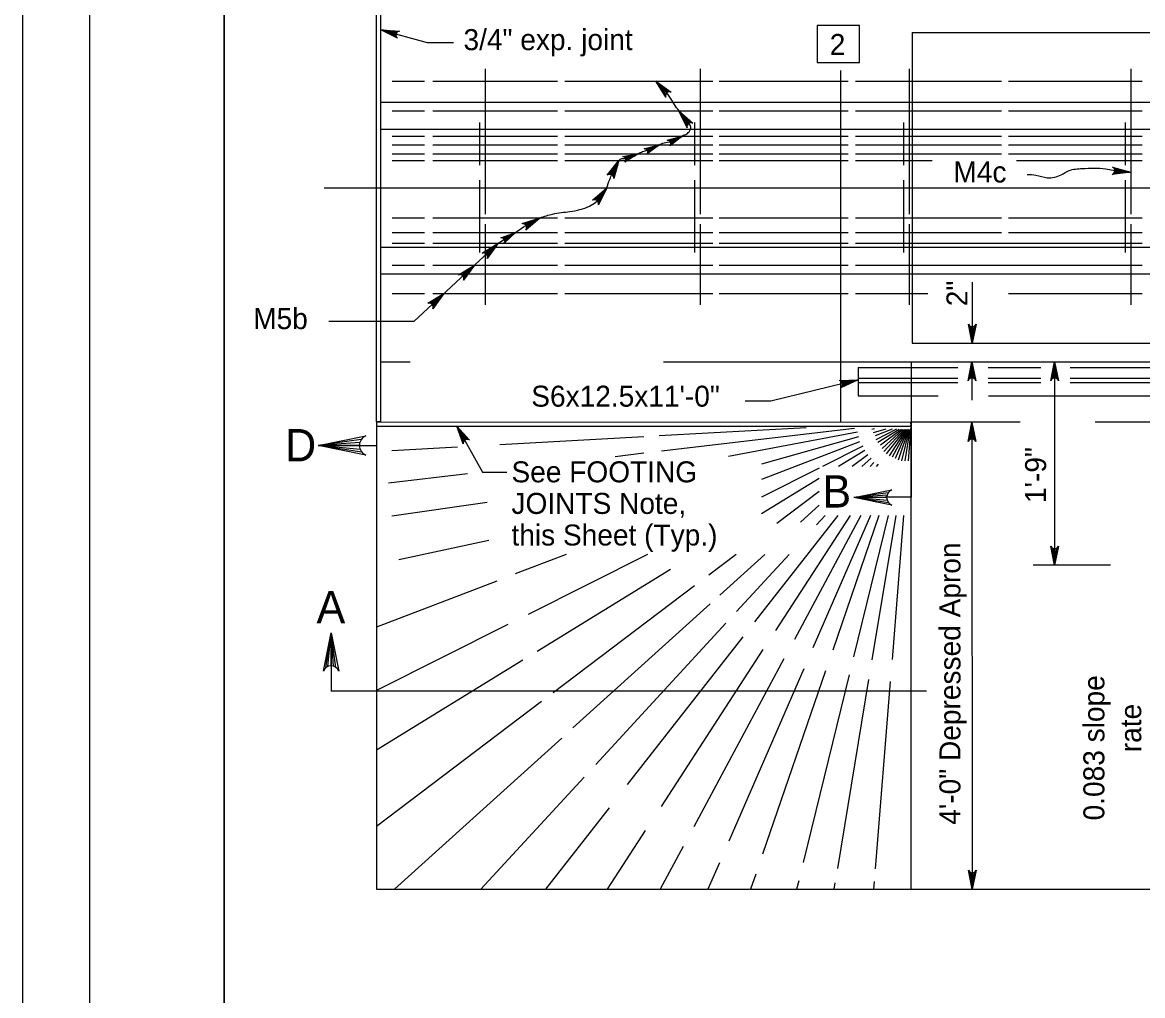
# Model space of a CAD drawing. Extents: x 0 to 34, y 0 to 22.
# Drawn here: x 0 to 8.32, y 10.41 to 17.63 of the extents above; entities that cross this region are included whole.
import ezdxf

# ---------------------------------------------------------------- set-up
doc = ezdxf.new("R2010")
doc.units = 0
for name, color, linetype in [('Default', 7, 'Continuous'), ('SH_Border', 7, 'Continuous'), ('SH_Cut_Line', 7, 'Continuous')]:
    doc.layers.add(name, color=color, linetype=linetype)

msp = doc.modelspace()

# ---------------------------------------------------------------- linework, layer by layer
at = {"layer": 'Default'}
for p, q in [((2.6299, 14.754), (2.6299, 18.1355)), ((2.6619, 14.754), (2.6619, 18.1355)), ((2.7767, 17.549), (2.6619, 17.58)), ((2.7759, 17.5375), (2.6619, 17.58)), ((2.7784, 17.5285), (2.6619, 17.58)), ((2.7802, 17.5571), (2.6619, 17.58)), ((2.7866, 17.5642), (2.6619, 17.58)), ((5.9052, 17.6119), (5.9052, 17.3364)), ((6.2195, 17.6119), (5.9052, 17.6119)), ((6.2195, 17.3364), (6.2195, 17.6119)), ((6.6102, 17.5605), (13.4816, 17.5605)), ((6.6102, 17.5605), (6.6102, 15.2526)), ((5.9052, 17.3364), (6.2195, 17.3364)), ((3.4374, 17.2901), (3.4374, 16.211)), ((5.0367, 17.2901), (5.0367, 16.211)), ((6.0797, 14.8717), (6.0797, 17.2778)), ((6.5879, 17.2901), (6.5879, 16.211)), ((8.2352, 17.2901), (8.2352, 16.211)), ((2.7462, 17.1978), (2.9867, 17.1978)), ((3.0502, 17.1978), (3.9757, 17.1978)), ((4.0302, 17.1978), (5.1292, 17.1978)), ((4.788, 17.1114), (4.7064, 17.1978)), ((4.7814, 17.1021), (4.7064, 17.1978)), ((4.7787, 17.0931), (4.7064, 17.1978)), ((4.7953, 17.1164), (4.7064, 17.1978)), ((4.8044, 17.1193), (4.7064, 17.1978)), ((5.1759, 17.1978), (6.1347, 17.1978)), ((6.1886, 17.1978), (7.2741, 17.1978)), ((7.3255, 17.1978), (8.3184, 17.1978)), ((2.6587, 17.0425), (13.2226, 17.0425)), ((2.7462, 16.9791), (2.9867, 16.9791)), ((3.0502, 16.9791), (3.9757, 16.9791)), ((4.0302, 16.9791), (5.1292, 16.9791)), ((4.9492, 16.8839), (4.878, 16.9791)), ((4.9416, 16.8754), (4.878, 16.9791)), ((4.938, 16.8668), (4.878, 16.9791)), ((4.957, 16.888), (4.878, 16.9791)), ((4.9665, 16.8899), (4.878, 16.9791)), ((5.1759, 16.9791), (6.1347, 16.9791)), ((6.1886, 16.9791), (7.2741, 16.9791)), ((7.3255, 16.9791), (8.3184, 16.9791)), ((2.6587, 16.8425), (13.2226, 16.8425)), ((3.3954, 16.892), (3.3954, 16.5743)), ((4.9947, 16.892), (4.9947, 16.5743)), ((6.5459, 16.892), (6.5459, 16.5743)), ((8.1932, 16.892), (8.1932, 16.5743)), ((2.7462, 16.7906), (2.9867, 16.7906)), ((3.0502, 16.7906), (3.9757, 16.7906)), ((4.0302, 16.7906), (5.1292, 16.7906)), ((4.8027, 16.7571), (4.9013, 16.7904)), ((4.8092, 16.7531), (4.9013, 16.7904)), ((4.8149, 16.7459), (4.9013, 16.7904)), ((4.8172, 16.739), (4.9013, 16.7904)), ((4.8173, 16.7311), (4.9013, 16.7904)), ((5.1759, 16.7906), (6.1347, 16.7906)), ((6.1886, 16.7906), (7.2741, 16.7906)), ((7.3255, 16.7906), (8.3184, 16.7906)), ((2.7462, 16.7252), (2.9867, 16.7252)), ((2.7462, 16.6597), (2.9867, 16.6597)), ((3.0502, 16.7252), (3.9757, 16.7252)), ((3.0502, 16.6597), (3.9757, 16.6597)), ((4.0302, 16.7252), (5.1292, 16.7252)), ((4.0302, 16.6597), (5.1292, 16.6597)), ((4.4713, 16.6351), (4.5727, 16.6594)), ((4.4774, 16.6306), (4.5727, 16.6594)), ((4.4826, 16.6228), (4.5727, 16.6594)), ((4.4837, 16.6079), (4.5727, 16.6594)), ((4.4842, 16.6157), (4.5727, 16.6594)), ((4.6312, 16.6935), (4.7305, 16.7252)), ((4.6377, 16.6893), (4.7305, 16.7252)), ((4.6433, 16.682), (4.7305, 16.7252)), ((4.6456, 16.675), (4.7305, 16.7252)), ((4.6457, 16.6671), (4.7305, 16.7252)), ((5.1759, 16.7252), (6.1347, 16.7252)), ((5.1759, 16.6597), (6.1347, 16.6597)), ((6.1886, 16.7252), (7.2741, 16.7252)), ((6.1886, 16.6597), (7.2741, 16.6597)), ((7.3255, 16.7252), (8.3184, 16.7252)), ((7.3255, 16.6597), (8.3184, 16.6597)), ((2.7462, 16.6092), (2.9867, 16.6092)), ((3.0502, 16.6092), (3.9757, 16.6092)), ((4.0302, 16.6092), (5.1292, 16.6092)), ((4.3584, 16.5055), (4.4325, 16.6092)), ((4.3678, 16.5061), (4.4325, 16.6092)), ((4.3787, 16.503), (4.4325, 16.6092)), ((4.386, 16.498), (4.4325, 16.6092)), ((4.3918, 16.4903), (4.4325, 16.6092)), ((5.1759, 16.6092), (6.1347, 16.6092)), ((6.1886, 16.6092), (6.7603, 16.6092)), ((7.3851, 16.6092), (8.3184, 16.6092)), ((8.1097, 16.5143), (8.2352, 16.5221)), ((8.1111, 16.551), (8.2352, 16.5221)), ((8.1146, 16.5225), (8.2352, 16.5221)), ((8.1152, 16.5425), (8.2352, 16.5221)), ((8.1165, 16.5312), (8.2352, 16.5221)), ((2.2418, 16.4059), (13.2226, 16.4059)), ((3.3954, 16.4632), (3.3954, 15.9257)), ((4.25, 16.3174), (4.3415, 16.4059)), ((4.2592, 16.3162), (4.3415, 16.4059)), ((4.2696, 16.3112), (4.3415, 16.4059)), ((4.2757, 16.3049), (4.3415, 16.4059)), ((4.2801, 16.2963), (4.3415, 16.4059)), ((4.9947, 16.4632), (4.9947, 15.9257)), ((6.5459, 16.4632), (6.5459, 15.9257)), ((8.1932, 16.4632), (8.1932, 15.9257)), ((2.7462, 16.183), (2.9867, 16.183)), ((3.0502, 16.183), (3.9757, 16.183)), ((3.7271, 16.1382), (3.8462, 16.183)), ((3.7352, 16.1335), (3.8462, 16.183)), ((3.7425, 16.1249), (3.8462, 16.183)), ((3.7457, 16.1166), (3.8462, 16.183)), ((3.7462, 16.107), (3.8462, 16.183)), ((4.0302, 16.183), (5.1292, 16.183)), ((5.1759, 16.183), (6.1347, 16.183)), ((6.1886, 16.183), (7.2741, 16.183)), ((7.3255, 16.183), (8.3184, 16.183)), ((2.7462, 16.0737), (2.9867, 16.0737)), ((3.0502, 16.0737), (3.9757, 16.0737)), ((3.4374, 16.1359), (3.4374, 15.5359)), ((3.5666, 16.0335), (3.6627, 16.0737)), ((3.5733, 16.0299), (3.6627, 16.0737)), ((3.5797, 16.023), (3.6627, 16.0737)), ((3.5825, 16.0163), (3.6627, 16.0737)), ((3.5832, 16.0085), (3.6627, 16.0737)), ((4.0302, 16.0737), (5.1292, 16.0737)), ((5.0367, 16.1359), (5.0367, 15.5359)), ((5.1759, 16.0737), (6.1347, 16.0737)), ((6.1886, 16.0737), (7.2741, 16.0737)), ((6.5879, 16.1359), (6.5879, 15.5359)), ((7.3255, 16.0737), (8.3184, 16.0737)), ((8.2352, 16.1359), (8.2352, 15.5359)), ((2.7462, 15.9945), (2.9867, 15.9945)), ((3.5347, 15.9945), (2.9075, 15.4138)), ((3.0502, 15.9945), (3.9757, 15.9945)), ((3.429, 15.9233), (3.5347, 15.9945)), ((3.438, 15.9205), (3.5347, 15.9945)), ((3.4472, 15.9138), (3.5347, 15.9945)), ((3.4522, 15.9065), (3.5347, 15.9945)), ((3.4549, 15.8973), (3.5347, 15.9945)), ((4.0302, 15.9945), (5.1292, 15.9945)), ((5.1759, 15.9945), (6.1347, 15.9945)), ((6.1886, 15.9945), (7.3255, 15.9945)), ((7.3255, 15.9945), (8.3184, 15.9945)), ((2.6587, 15.9659), (7.3622, 15.9659)), ((7.3252, 15.9659), (13.2226, 15.9659)), ((2.7462, 15.832), (2.9867, 15.832)), ((3.0502, 15.832), (3.9757, 15.832)), ((3.253, 15.7611), (3.3587, 15.8323)), ((3.262, 15.7585), (3.3587, 15.8323)), ((3.2712, 15.7517), (3.3587, 15.8323)), ((3.2762, 15.7444), (3.3587, 15.8323)), ((3.2789, 15.7352), (3.3587, 15.8323)), ((4.0302, 15.832), (5.1292, 15.832)), ((5.1759, 15.832), (6.1347, 15.832)), ((6.1886, 15.832), (7.3255, 15.832)), ((7.3255, 15.832), (8.3184, 15.832)), ((2.6587, 15.7663), (7.3252, 15.7663)), ((7.3252, 15.7663), (13.2226, 15.7663)), ((7.0568, 15.7059), (7.0568, 15.2526)), ((2.7462, 15.621), (2.9867, 15.621)), ((3.0259, 15.5497), (3.1316, 15.6208)), ((3.0349, 15.547), (3.1316, 15.6208)), ((3.0441, 15.5402), (3.1316, 15.6208)), ((3.0491, 15.5329), (3.1316, 15.6208)), ((3.0502, 15.621), (3.9757, 15.621)), ((3.0518, 15.5237), (3.1316, 15.6208)), ((4.0302, 15.621), (5.1292, 15.621)), ((5.1759, 15.621), (6.1347, 15.621)), ((6.1886, 15.621), (6.7267, 15.621)), ((7.3255, 15.621), (8.3184, 15.621)), ((2.9075, 15.4138), (2.2767, 15.4138)), ((7.0389, 15.3808), (7.0568, 15.2526)), ((7.0477, 15.3765), (7.0568, 15.2526)), ((7.0767, 15.3823), (7.0568, 15.2526)), ((7.0683, 15.3774), (7.0568, 15.2526)), ((7.0568, 15.3751), (7.0568, 15.2526)), ((6.6102, 15.2526), (13.4572, 15.2526)), ((2.6587, 15.1145), (2.8801, 15.1145)), ((4.7623, 15.1145), (13.2169, 15.1145)), ((6.2088, 15.0704), (6.2088, 14.8604)), ((6.2088, 15.0704), (6.9505, 15.0704)), ((6.6032, 15.1145), (6.6032, 14.6664)), ((7.0352, 14.9849), (7.055, 15.1145)), ((7.0435, 14.9898), (7.055, 15.1145)), ((7.055, 14.992), (7.055, 15.1145)), ((7.0641, 14.9907), (7.055, 15.1145)), ((7.0729, 14.9864), (7.055, 15.1145)), ((7.055, 15.1145), (7.055, 14.8292)), ((7.1763, 15.0704), (7.5665, 15.0704)), ((7.6492, 14.9849), (7.6689, 15.1145)), ((7.6574, 14.9898), (7.6689, 15.1145)), ((7.6689, 15.1145), (7.6689, 13.6028)), ((7.6689, 14.992), (7.6689, 15.1145)), ((7.678, 14.9907), (7.6689, 15.1145)), ((7.6869, 14.9864), (7.6689, 15.1145)), ((7.7847, 15.0704), (13.2147, 15.0704)), ((6.2088, 14.9931), (6.9505, 14.9931)), ((7.1763, 14.9931), (7.5665, 14.9931)), ((7.7847, 14.9931), (13.2147, 14.9931)), ((6.2088, 14.9785), (5.5602, 14.8218)), ((6.0818, 14.9688), (6.2088, 14.9785)), ((6.0883, 14.962), (6.2088, 14.9785)), ((6.0916, 14.9334), (6.2088, 14.9785)), ((6.093, 14.9516), (6.2088, 14.9785)), ((6.0937, 14.9427), (6.2088, 14.9785)), ((6.2088, 14.9605), (6.9505, 14.9605)), ((7.1763, 14.9605), (7.5665, 14.9605)), ((7.7847, 14.9605), (13.2147, 14.9605)), ((5.5602, 14.8218), (5.3711, 14.8218)), ((6.0797, 14.6664), (6.0797, 14.8717)), ((6.2088, 14.8604), (6.8027, 14.8604)), ((7.1775, 14.8604), (13.2147, 14.8604)), ((2.6299, 14.6664), (2.6299, 14.754)), ((2.6619, 14.6664), (2.6619, 14.754)), ((2.6299, 14.6664), (2.6587, 14.6664)), ((2.6299, 14.6664), (2.6299, 14.5643)), ((2.6299, 14.6664), (2.6299, 14.4918)), ((2.6619, 14.6664), (2.6331, 14.6664)), ((2.6587, 14.6664), (6.5998, 14.6661)), ((6.6032, 14.6664), (6.5802, 14.379)), ((6.6032, 14.6664), (6.5983, 14.6368)), ((6.6032, 14.6664), (6.599, 14.649)), ((6.6032, 14.6664), (6.5992, 14.6548)), ((6.6032, 14.6664), (6.5994, 14.6575)), ((6.6032, 14.6664), (6.5995, 14.6594)), ((6.6032, 14.6664), (6.5996, 14.6607)), ((6.6032, 14.6664), (6.5997, 14.6646)), ((6.6032, 14.6664), (6.5997, 14.6642)), ((6.6032, 14.6664), (6.5997, 14.6637)), ((6.6032, 14.6664), (6.5997, 14.6631)), ((6.6032, 14.6664), (6.5997, 14.6625)), ((6.6032, 14.6664), (6.5997, 14.6617)), ((6.6032, 14.6664), (6.5998, 14.6661)), ((6.6032, 14.6664), (6.5998, 14.6657)), ((6.6032, 14.6664), (6.5998, 14.6654)), ((6.6032, 14.6664), (6.5998, 14.666)), ((6.6032, 14.6664), (6.5998, 14.665)), ((6.6032, 11.1951), (6.6032, 14.6664)), ((6.6032, 14.6664), (6.6032, 14.1067)), ((6.6032, 14.6664), (6.7953, 14.6664)), ((6.7953, 14.6664), (7.4136, 14.6664)), ((7.0352, 14.5326), (7.055, 14.6623)), ((7.0435, 14.5375), (7.055, 14.6623)), ((7.055, 14.6623), (7.0568, 11.1951)), ((7.055, 14.5398), (7.055, 14.6623)), ((7.0641, 14.5385), (7.055, 14.6623)), ((7.0729, 14.5341), (7.055, 14.6623)), ((7.9699, 14.6664), (9.1479, 14.6664)), ((2.6299, 14.6349), (6.5998, 14.6347)), ((3.2884, 14.533), (3.227, 14.6349)), ((3.28, 14.5255), (3.227, 14.6349)), ((3.2755, 14.5171), (3.227, 14.6349)), ((3.2966, 14.5365), (3.227, 14.6349)), ((3.3061, 14.5373), (3.227, 14.6349)), ((5.8236, 14.6232), (4.7308, 14.5628)), ((6.1832, 14.6171), (4.7482, 14.449)), ((6.2051, 14.5909), (5.2467, 14.4092)), ((6.3306, 14.6147), (6.3122, 14.6112)), ((6.4143, 14.6133), (6.3208, 14.587)), ((6.4627, 14.6125), (6.3348, 14.5634)), ((6.4948, 14.6119), (6.3417, 14.535)), ((6.5139, 14.6115), (6.3553, 14.5143)), ((6.5305, 14.6113), (6.3766, 14.4949)), ((6.5422, 14.6111), (6.3868, 14.4706)), ((6.5522, 14.611), (6.4003, 14.446)), ((6.5597, 14.6108), (6.4186, 14.4305)), ((6.567, 14.6107), (6.4397, 14.4151)), ((6.5733, 14.6105), (6.4629, 14.4051)), ((6.579, 14.6105), (6.4848, 14.394)), ((6.584, 14.6104), (6.5057, 14.3826)), ((6.5895, 14.6103), (6.5326, 14.378)), ((6.594, 14.6102), (6.5555, 14.3773)), ((2.5177, 14.5366), (2.1972, 14.4918)), ((2.5069, 14.5145), (2.1972, 14.4918)), ((2.1972, 14.4918), (2.6299, 14.4918)), ((2.5036, 14.4918), (2.1972, 14.4918)), ((2.5092, 14.463), (2.1972, 14.4918)), ((2.5216, 14.4422), (2.1972, 14.4918)), ((2.6299, 14.5643), (2.6299, 11.1951)), ((4.6168, 14.5565), (3.5461, 14.4973)), ((6.2131, 14.5567), (5.4906, 14.3538)), ((6.2187, 14.5188), (5.4906, 14.2394)), ((6.2435, 14.4856), (5.9442, 14.3354)), ((3.2322, 14.4799), (2.7442, 14.4529)), ((4.6183, 14.4338), (4.4033, 14.4086)), ((6.2582, 14.4546), (6.0638, 14.3354)), ((6.2808, 14.4225), (6.1657, 14.3354)), ((5.9209, 14.3236), (5.4906, 14.1075)), ((6.3063, 14.3978), (6.2373, 14.3354)), ((6.3258, 14.3652), (6.2984, 14.3354)), ((6.3571, 14.352), (6.3442, 14.3354)), ((3.3068, 14.2801), (2.7193, 14.2113)), ((5.9209, 14.2477), (5.4906, 13.9837)), ((5.9209, 14.1501), (5.6062, 13.9121)), ((3.452, 14.0689), (2.7437, 13.9667)), ((6.4327, 14.1408), (6.1763, 14.105)), ((6.424, 14.123), (6.1763, 14.105)), ((6.4214, 14.105), (6.1763, 14.105)), ((6.4259, 14.0819), (6.1763, 14.105)), ((6.4357, 14.0653), (6.1763, 14.105)), ((6.485, 14.1067), (6.4113, 14.1067)), ((6.6032, 14.1067), (6.485, 14.1067)), ((5.9209, 14.0491), (5.7809, 13.9225)), ((6.0593, 13.9716), (5.4404, 13.1811)), ((6.151, 13.9716), (5.5955, 13.1182)), ((6.23, 13.9716), (5.7355, 13.051)), ((6.3012, 13.9716), (5.8735, 12.9881)), ((5.9632, 13.9716), (5.9003, 13.9034)), ((6.3643, 13.9716), (6.0205, 12.9714)), ((6.4329, 13.9716), (6.1754, 12.9216)), ((6.4884, 13.9716), (6.311, 12.8983)), ((6.5474, 13.9716), (6.4616, 12.9022)), ((3.4657, 13.785), (2.7977, 13.6416)), ((4.0402, 13.6827), (3.6623, 13.5377)), ((4.6447, 13.6827), (3.7565, 13.2365)), ((5.3031, 13.6827), (5.0993, 13.5286)), ((5.5157, 13.6827), (5.1811, 13.3801)), ((5.697, 13.6827), (5.3052, 13.2575)), ((7.651, 13.731), (7.6689, 13.6028)), ((7.6599, 13.7266), (7.6689, 13.6028)), ((7.6887, 13.7325), (7.6689, 13.6028)), ((7.6805, 13.7275), (7.6689, 13.6028)), ((7.6689, 13.7253), (7.6689, 13.6028)), ((4.8164, 13.5701), (3.8244, 12.9615)), ((8.085, 13.6028), (7.5091, 13.6028)), ((3.5243, 13.4848), (2.6299, 13.1415)), ((4.9936, 13.4486), (3.9428, 12.6536)), ((5.1097, 13.3156), (4.09, 12.3933)), ((3.6066, 13.1612), (2.6299, 12.6706)), ((5.2262, 13.1715), (4.2598, 12.1226)), ((2.2537, 12.84), (2.2933, 13.0994)), ((2.2702, 12.8498), (2.2933, 13.0994)), ((2.2933, 13.0994), (2.2933, 12.6667)), ((2.2933, 12.8543), (2.2933, 13.0994)), ((2.3114, 12.8517), (2.2933, 13.0994)), ((2.3292, 12.843), (2.2933, 13.0994)), ((5.3532, 13.0697), (4.4941, 11.9725)), ((5.5024, 12.9753), (4.7447, 11.811)), ((5.6585, 12.9078), (4.9878, 11.6593)), ((3.7176, 12.896), (2.6299, 12.2287)), ((5.8062, 12.8333), (5.2492, 11.5523)), ((5.9677, 12.8182), (5.4996, 11.4566)), ((6.1425, 12.7871), (5.8012, 11.3949)), ((6.287, 12.7535), (6.0548, 11.349)), ((6.4485, 12.7395), (6.3366, 11.3464)), ((6.7182, 12.6667), (2.2933, 12.6667)), ((3.8578, 12.5893), (2.6299, 11.6604)), ((4.0075, 12.3185), (2.7654, 11.1951)), ((4.1727, 12.028), (3.4054, 11.1951)), ((4.3591, 11.8), (3.8855, 11.1951)), ((4.6278, 11.6316), (4.3437, 11.1951)), ((4.909, 11.5125), (4.7385, 11.1951)), ((5.1792, 11.3915), (5.0938, 11.1951)), ((7.0389, 11.3234), (7.0568, 11.1951)), ((7.0477, 11.319), (7.0568, 11.1951)), ((7.0767, 11.3249), (7.0568, 11.1951)), ((7.0683, 11.32), (7.0568, 11.1951)), ((5.4481, 11.3068), (5.4097, 11.1951)), ((5.7677, 11.2585), (5.7522, 11.1951)), ((6.0373, 11.2432), (6.0294, 11.1951)), ((6.329, 11.2515), (6.3244, 11.1951)), ((7.0568, 11.3177), (7.0568, 11.1951)), ((2.6299, 11.1951), (18.4777, 11.1951))]:
    msp.add_line(p, q, dxfattribs=at)
for points in [[(2.7874, 17.5175), (2.6619, 17.58), (2.8017, 17.5706)], [(2.6619, 17.58), (3.008, 17.4844), (3.204, 17.4844)], [(4.7807, 17.079), (4.7064, 17.1978), (4.8207, 17.1167)], [(4.9383, 16.8525), (4.878, 16.9791), (4.9823, 16.8855)], [(4.7911, 16.7588), (4.9013, 16.7904), (4.8117, 16.7189)], [(4.4599, 16.6378), (4.5727, 16.6594), (4.477, 16.5963)], [(4.6197, 16.6953), (4.7305, 16.7252), (4.6397, 16.655)], [(4.3459, 16.499), (4.4325, 16.6092), (4.395, 16.4741)], [(8.1002, 16.56), (8.2352, 16.5221), (8.096, 16.5052)], [(4.2364, 16.3131), (4.3415, 16.4059), (4.2802, 16.2798)], [(3.7129, 16.1399), (3.8462, 16.183), (3.7398, 16.0919)], [(3.555, 16.0343), (3.6627, 16.0737), (3.5784, 15.996)], [(3.4149, 15.9215), (3.5347, 15.9945), (3.4522, 15.8811)], [(3.239, 15.7594), (3.3587, 15.8323), (3.2762, 15.719)], [(3.0118, 15.5479), (3.1316, 15.6208), (3.0491, 15.5075)], [(7.0852, 15.3942), (7.0568, 15.2526), (7.0285, 15.3942)], [(7.0267, 14.973), (7.055, 15.1145), (7.0833, 14.973)], [(7.6407, 14.973), (7.6689, 15.1145), (7.6972, 14.973)], [(6.0687, 14.9742), (6.2088, 14.9785), (6.0812, 14.9207)], [(7.0267, 14.5207), (7.055, 14.6623), (7.0833, 14.5207)], [(3.2745, 14.503), (3.227, 14.6349), (3.3215, 14.5314)], [(3.227, 14.6349), (3.4185, 14.2932), (3.5981, 14.2932)], [(2.5512, 14.421), (2.1972, 14.4918), (2.5512, 14.5626)], [(6.4595, 14.0483), (6.1763, 14.105), (6.4595, 14.1615)], [(7.6972, 13.7444), (7.6689, 13.6028), (7.6407, 13.7444)], [(2.2367, 12.8162), (2.2933, 13.0994), (2.3499, 12.8162)], [(7.0852, 11.3368), (7.0568, 11.1951), (7.0285, 11.3368)]]:
    msp.add_lwpolyline(points, dxfattribs=at)
for centre, radius, start, end in [((7.0568, 15.4057), 0.0306, 202.08782, 337.91395), ((7.055, 14.9615), 0.0306, 22.08782, 157.91395), ((7.669, 14.9615), 0.0306, 22.08782, 157.91395), ((2.5799, 14.4919), 0.0764, 112.08782, 247.91395), ((7.055, 14.5093), 0.0306, 22.08782, 157.91395), ((6.4824, 14.105), 0.0611, 112.08782, 247.91395), ((7.6689, 13.7558), 0.0306, 202.08782, 337.91395), ((2.2933, 12.7933), 0.0611, 22.08782, 157.91395), ((7.0568, 11.3482), 0.0306, 202.08782, 337.91395)]:
    msp.add_arc(centre, radius, start, end, dxfattribs=at)
for centre, major_axis, start_param, end_param in [((2.8053, 17.5412), (-0.0296, 0.0021), 4.904467, 7.27508), ((4.8084, 17.0898), (0.0297, 0), 1.141672, 3.512285), ((4.967, 16.8601), (0.0297, 0), 1.027626, 3.398239), ((4.7932, 16.7347), (0.0243, 0), 5.57401, 7.944623), ((4.6216, 16.6711), (0.0243, 0), 5.55876, 7.929373), ((4.46, 16.6137), (0.0243, 0), 5.483661, 7.854274), ((4.3654, 16.4766), (0.0297, 0), 6.20027, 8.570883), ((8.087, 16.5335), (0.0297, 0), 5.021719, 7.392332), ((4.2516, 16.2876), (0.0297, 0), 6.01866, 8.389273), ((3.7166, 16.1104), (0.0297, 0), 5.608673, 7.979286), ((3.5589, 16.0103), (0.0243, 0), 5.645901, 8.016514), ((3.4254, 15.8938), (0.0297, 0), 5.842591, 8.213204), ((3.2494, 15.7316), (0.0297, 0), 5.842591, 8.213204), ((3.0223, 15.5201), (0.0297, 0), 5.842591, 8.213204), ((6.0641, 14.9449), (0.0297, 0), 5.325468, 7.696081), ((3.3037, 14.5076), (0.0232, 0.0184), 0.257527, 2.62814)]:
    msp.add_ellipse(centre, major_axis=major_axis, ratio=0.999895, start_param=start_param, end_param=end_param, dxfattribs=at)
for points in [[(4.8786, 16.9783), (4.8441, 17.0249), (4.8064, 17.0874), (4.7617, 17.1392), (4.7064, 17.1978)], [(4.9017, 16.7906), (4.9112, 16.7965), (4.9289, 16.8026), (4.9527, 16.8217), (4.9649, 16.8415), (4.9669, 16.8591), (4.9608, 16.8707), (4.931, 16.9087), (4.9011, 16.9482), (4.878, 16.9791)], [(4.7305, 16.7252), (4.7483, 16.734), (4.7904, 16.7449), (4.8652, 16.7666), (4.9017, 16.7906)], [(4.4325, 16.6092), (4.4422, 16.6197), (4.4692, 16.6234), (4.5145, 16.6283), (4.5732, 16.6597)], [(4.5732, 16.6597), (4.5989, 16.671), (4.6364, 16.6847), (4.6729, 16.6965), (4.7305, 16.7252)], [(4.3415, 16.4059), (4.3639, 16.4689), (4.4042, 16.5535), (4.4325, 16.6092)], [(7.4657, 16.5045), (7.5302, 16.5005), (7.6144, 16.481), (7.7182, 16.5025), (7.7768, 16.5339), (7.8727, 16.5496), (8.0487, 16.5476), (8.1583, 16.528), (8.2352, 16.5221)], [(3.8462, 16.183), (3.9397, 16.2113), (4.068, 16.23), (4.2133, 16.2695), (4.2612, 16.3003), (4.3415, 16.4059)], [(3.6627, 16.0737), (3.7067, 16.1048), (3.8462, 16.183)], [(3.5347, 15.9945), (3.5882, 16.0282), (3.6627, 16.0737)]]:
    msp.add_spline(points, degree=3, dxfattribs=at)
at = {"layer": 'SH_Border'}
for points in [[(0.5, 21.5), (1.5, 21.5), (1.5, 0.5), (0.5, 0.5)], [(1.5, 21.5), (33.5, 21.5), (33.5, 0.5), (1.5, 0.5)]]:
    msp.add_lwpolyline(points, close=True, dxfattribs=at)
at = {"layer": 'SH_Cut_Line'}
msp.add_lwpolyline([(0, 0), (34, 0), (34, 22), (0, 22)], close=True, dxfattribs=at)

# ---------------------------------------------------------------- texts
at = {"layer": 'Default'}
for s, height, p in [('3/4" exp. joint ', 0.156, (3.2772, 17.4289)), ('2', 0.156, (5.9985, 17.3928)), ('M4c', 0.156, (6.9172, 16.4457)), ('M5b', 0.156, (1.7148, 15.3561)), ('S6x12.5x11\'-0"', 0.156, (3.7807, 14.78)), ('D', 0.24, (1.9512, 14.3742)), ('See FOOTING', 0.156, (3.6337, 14.218)), ('B', 0.24, (5.9433, 14.0306)), ('JOINTS Note,', 0.156, (3.6337, 13.9834)), ('this Sheet (Typ.)', 0.156, (3.6337, 13.7487)), ('A', 0.24, (2.1848, 13.1711))]:
    msp.add_text(s, height=height, dxfattribs=at).set_placement(p)
for s, p in [('2"', (7.0215, 15.5263)), ('1\'-9"', (7.6059, 14.0645)), ('4\'-0" Depressed Apron', (6.9694, 11.6745)), ('0.083 slope', (8.0387, 11.7065)), ('rate', (8.3127, 12.2132))]:
    msp.add_text(s, height=0.156, rotation=90, dxfattribs=at).set_placement(p)

doc.saveas('drawing.dxf')
